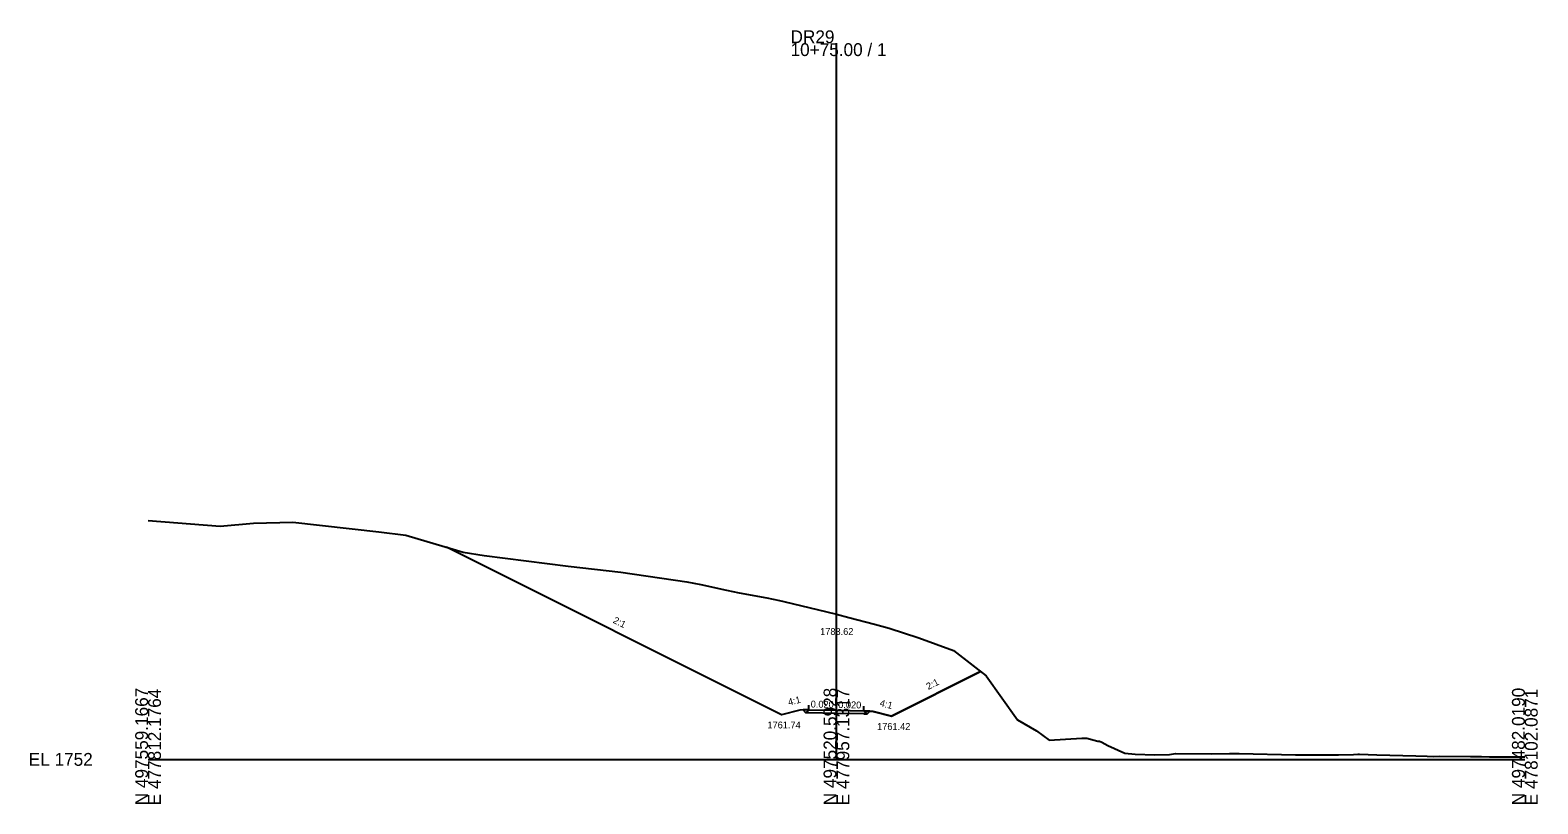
# Model space of a CAD drawing. Extents: x -26 to 303, y -10 to 4734.
# Drawn here: x -25.7 to 302.8, y 1490.3 to 1658.9 of the extents above; entities that cross this region are included whole.
import ezdxf

# ---------------------------------------------------------------- set-up
doc = ezdxf.new("R2010")
doc.units = 0
for name, color, linetype in [('Exist Cross Section Cell', 7, 'Continuous'), ('Exist XS Center Line Elevation Label', 7, 'Continuous'), ('Exist XS Ground Line', 7, 'Continuous'), ('Prop XS Ditch Slope Text', 7, 'Continuous'), ('Prop XS Ditch Standard Text', 7, 'Continuous'), ('Prop XS Dump Level', 7, 'Continuous'), ('Prop XS Earthwork Shape', 7, 'Continuous'), ('Prop XS EOT Tick Mark', 7, 'Continuous'), ('Prop XS Finish Grade', 7, 'Continuous'), ('Prop XS Finish Grade Earthwork', 7, 'Continuous'), ('Prop XS Finish Grade Pavement', 7, 'Continuous'), ('Prop XS Pvmt Edge Slope', 7, 'Continuous'), ('Prop XS SE Text', 7, 'Continuous'), ('Prop XS Shoulder Borrow Shape', 7, 'Continuous'), ('Prop XS Side Slope Text', 7, 'Continuous'), ('Prop XS Subgrade Earthwork', 7, 'Continuous')]:
    doc.layers.add(name, color=color, linetype=linetype)

msp = doc.modelspace()

# ---------------------------------------------------------------- linework, layer by layer
at = {"layer": 'Exist Cross Section Cell'}
for p, q in [((150, 1500), (150, 1656.08)), ((0, 1500), (150, 1500)), ((150, 1500), (300, 1500))]:
    msp.add_line(p, q, dxfattribs=at)
at = {"layer": 'Exist XS Ground Line'}
msp.add_lwpolyline([(0, 1552.03), (15.71, 1550.86), (22.98, 1551.45), (31.57, 1551.72), (50.29, 1549.59), (56.19, 1548.86), (68.68, 1545.13), (73.23, 1544.45), (91.55, 1542.14), (103.02, 1540.8), (117.43, 1538.71), (120.43, 1538.11), (126.06, 1536.88), (128.82, 1536.31), (134.83, 1535.22), (137.57, 1534.65), (138.57, 1534.4), (147.92, 1532.17), (150, 1531.62), (152.67, 1530.92), (158.27, 1529.45), (161.52, 1528.56), (167.95, 1526.46), (175.49, 1523.76), (182.62, 1518.18), (189.47, 1508.65), (193.6, 1506.21), (196.36, 1504.18), (203.48, 1504.59), (204.58, 1504.65), (206.97, 1503.98), (207.35, 1503.94), (207.84, 1503.78), (209.13, 1503.01), (212.83, 1501.36), (215.12, 1501.16), (219.4, 1501.02), (222.6, 1501.08), (223.89, 1501.27), (231.68, 1501.23), (235.68, 1501.3), (237.75, 1501.28), (250.01, 1501), (258.41, 1501), (259.38, 1501.02), (262.65, 1501.09), (263.61, 1501.1), (264.01, 1501.1), (267.79, 1500.99), (276.23, 1500.76), (278.73, 1500.69), (280.01, 1500.66), (281.39, 1500.7), (288.17, 1500.64), (289.87, 1500.62), (290.54, 1500.61), (292.31, 1500.59), (293.52, 1500.58), (294.83, 1500.55), (295.29, 1500.55), (295.78, 1500.55), (297.52, 1500.57), (300, 1500.57)], dxfattribs=at)
at = {"layer": 'Prop XS Dump Level'}
for p, q in [((144, 1510.82), (150, 1510.7)), ((150, 1510.7), (156, 1510.58))]:
    msp.add_line(p, q, dxfattribs=at)
at = {"layer": 'Prop XS Earthwork Shape'}
for points in [[(156, 1509.91), (150, 1510.03), (144, 1510.15), (143.35, 1510.17), (142.74, 1510.77), (142, 1510.74), (138, 1509.74), (65.04, 1546.22), (68.68, 1545.13), (73.23, 1544.45), (91.55, 1542.14), (103.02, 1540.8), (117.43, 1538.71), (120.43, 1538.11), (126.06, 1536.88), (128.82, 1536.31), (134.83, 1535.22), (137.57, 1534.65), (138.57, 1534.4), (147.92, 1532.17), (150, 1531.62), (152.67, 1530.92), (158.27, 1529.45), (161.52, 1528.56), (167.95, 1526.46), (175.49, 1523.76), (181.41, 1519.13), (162, 1509.42), (158, 1510.42), (157.26, 1510.48), (156.68, 1509.9)], [(143.35, 1510.17), (142.74, 1510.77), (142, 1510.74), (138, 1509.74), (65.04, 1546.22), (68.68, 1545.13), (73.23, 1544.45), (91.55, 1542.14), (103.02, 1540.8), (117.43, 1538.71), (120.43, 1538.11), (126.06, 1536.88), (128.82, 1536.31), (134.83, 1535.22), (137.57, 1534.65), (138.57, 1534.4), (147.92, 1532.17), (150, 1531.62), (152.67, 1530.92), (158.27, 1529.45), (161.52, 1528.56), (167.95, 1526.46), (175.49, 1523.76), (181.41, 1519.13), (162, 1509.42), (158, 1510.42), (157.26, 1510.48), (156.68, 1509.9), (156, 1509.91), (150, 1510.03), (144, 1510.15)]]:
    msp.add_lwpolyline(points, close=True, dxfattribs=at)
at = {"layer": 'Prop XS EOT Tick Mark'}
for p, q in [((144, 1510.82), (144, 1511.82)), ((156, 1510.58), (156, 1511.58))]:
    msp.add_line(p, q, dxfattribs=at)
at = {"layer": 'Prop XS Finish Grade'}
for p, q in [((144, 1510.82), (142.74, 1510.77)), ((156, 1510.58), (157.26, 1510.48))]:
    msp.add_line(p, q, dxfattribs=at)
at = {"layer": 'Prop XS Finish Grade Earthwork'}
for p, q in [((138, 1509.74), (65.04, 1546.22)), ((162, 1509.42), (181.41, 1519.13)), ((142, 1510.74), (138, 1509.74)), ((142.74, 1510.77), (142, 1510.74)), ((157.26, 1510.48), (158, 1510.42)), ((158, 1510.42), (162, 1509.42))]:
    msp.add_line(p, q, dxfattribs=at)
at = {"layer": 'Prop XS Finish Grade Pavement'}
for p, q in [((144, 1510.82), (150, 1510.7)), ((150, 1510.7), (156, 1510.58))]:
    msp.add_line(p, q, dxfattribs=at)
at = {"layer": 'Prop XS Pvmt Edge Slope'}
for p, q in [((144, 1510.82), (143.35, 1510.17)), ((156, 1510.58), (156.68, 1509.9))]:
    msp.add_line(p, q, dxfattribs=at)
at = {"layer": 'Prop XS Shoulder Borrow Shape'}
for points in [[(144, 1510.82), (142.74, 1510.77), (143.35, 1510.17)], [(156.68, 1509.9), (157.26, 1510.48), (156, 1510.58)]]:
    msp.add_lwpolyline(points, close=True, dxfattribs=at)
at = {"layer": 'Prop XS Subgrade Earthwork'}
for p, q in [((143.35, 1510.17), (142.74, 1510.77)), ((144, 1510.15), (143.35, 1510.17)), ((150, 1510.03), (144, 1510.15)), ((156, 1509.91), (150, 1510.03)), ((156, 1509.91), (156.68, 1509.9)), ((156.68, 1509.9), (157.26, 1510.48))]:
    msp.add_line(p, q, dxfattribs=at)

# ---------------------------------------------------------------- texts
at = {"layer": 'Exist Cross Section Cell'}
for s, p in [('10+75.00 / 1', (140, 1653.28)), ('DR29', (140, 1656.08)), ('EL 1752', (-26, 1498.6))]:
    msp.add_text(s, height=2.8, dxfattribs=at).set_placement(p)
for s, p in [('N 497559.1667', (0, 1490)), ('E 477812.1764', (2.8, 1490)), ('N 497520.5928', (150, 1490)), ('E 477957.1317', (152.8, 1490)), ('N 497482.0190', (300, 1490)), ('E 478102.0871', (302.8, 1490))]:
    msp.add_text(s, height=2.8, rotation=90, dxfattribs=at).set_placement(p)
at = {"layer": 'Exist XS Center Line Elevation Label'}
msp.add_text('1783.62', height=1.5, dxfattribs=at).set_placement((146.45, 1527.12))
at = {"layer": 'Prop XS Ditch Slope Text'}
for rotation, p in [(14.0362, (139.64, 1511.7)), (345.9638, (159.33, 1511.63))]:
    msp.add_text('4:1', height=1.5, rotation=rotation, dxfattribs=at).set_placement(p)
at = {"layer": 'Prop XS Ditch Standard Text'}
for s, p in [('1761.74', (134.96, 1506.74)), ('1761.42', (158.86, 1506.42))]:
    msp.add_text(s, height=1.5, dxfattribs=at).set_placement(p)
at = {"layer": 'Prop XS Dump Level'}
for p in [(142, 1510.7), (158, 1510.38)]:
    msp.add_text('Case1', height=0.04, dxfattribs=at).set_placement(p)
at = {"layer": 'Prop XS SE Text'}
for p in [(144.38, 1511.31), (150.38, 1511.19)]:
    msp.add_text('0.020', height=1.5, rotation=358.8542, dxfattribs=at).set_placement(p)
at = {"layer": 'Prop XS Side Slope Text'}
for rotation, p in [(333.4349, (101.18, 1529.83)), (26.5651, (170.02, 1515.11))]:
    msp.add_text('2:1', height=1.5, rotation=rotation, dxfattribs=at).set_placement(p)

doc.saveas('drawing.dxf')
